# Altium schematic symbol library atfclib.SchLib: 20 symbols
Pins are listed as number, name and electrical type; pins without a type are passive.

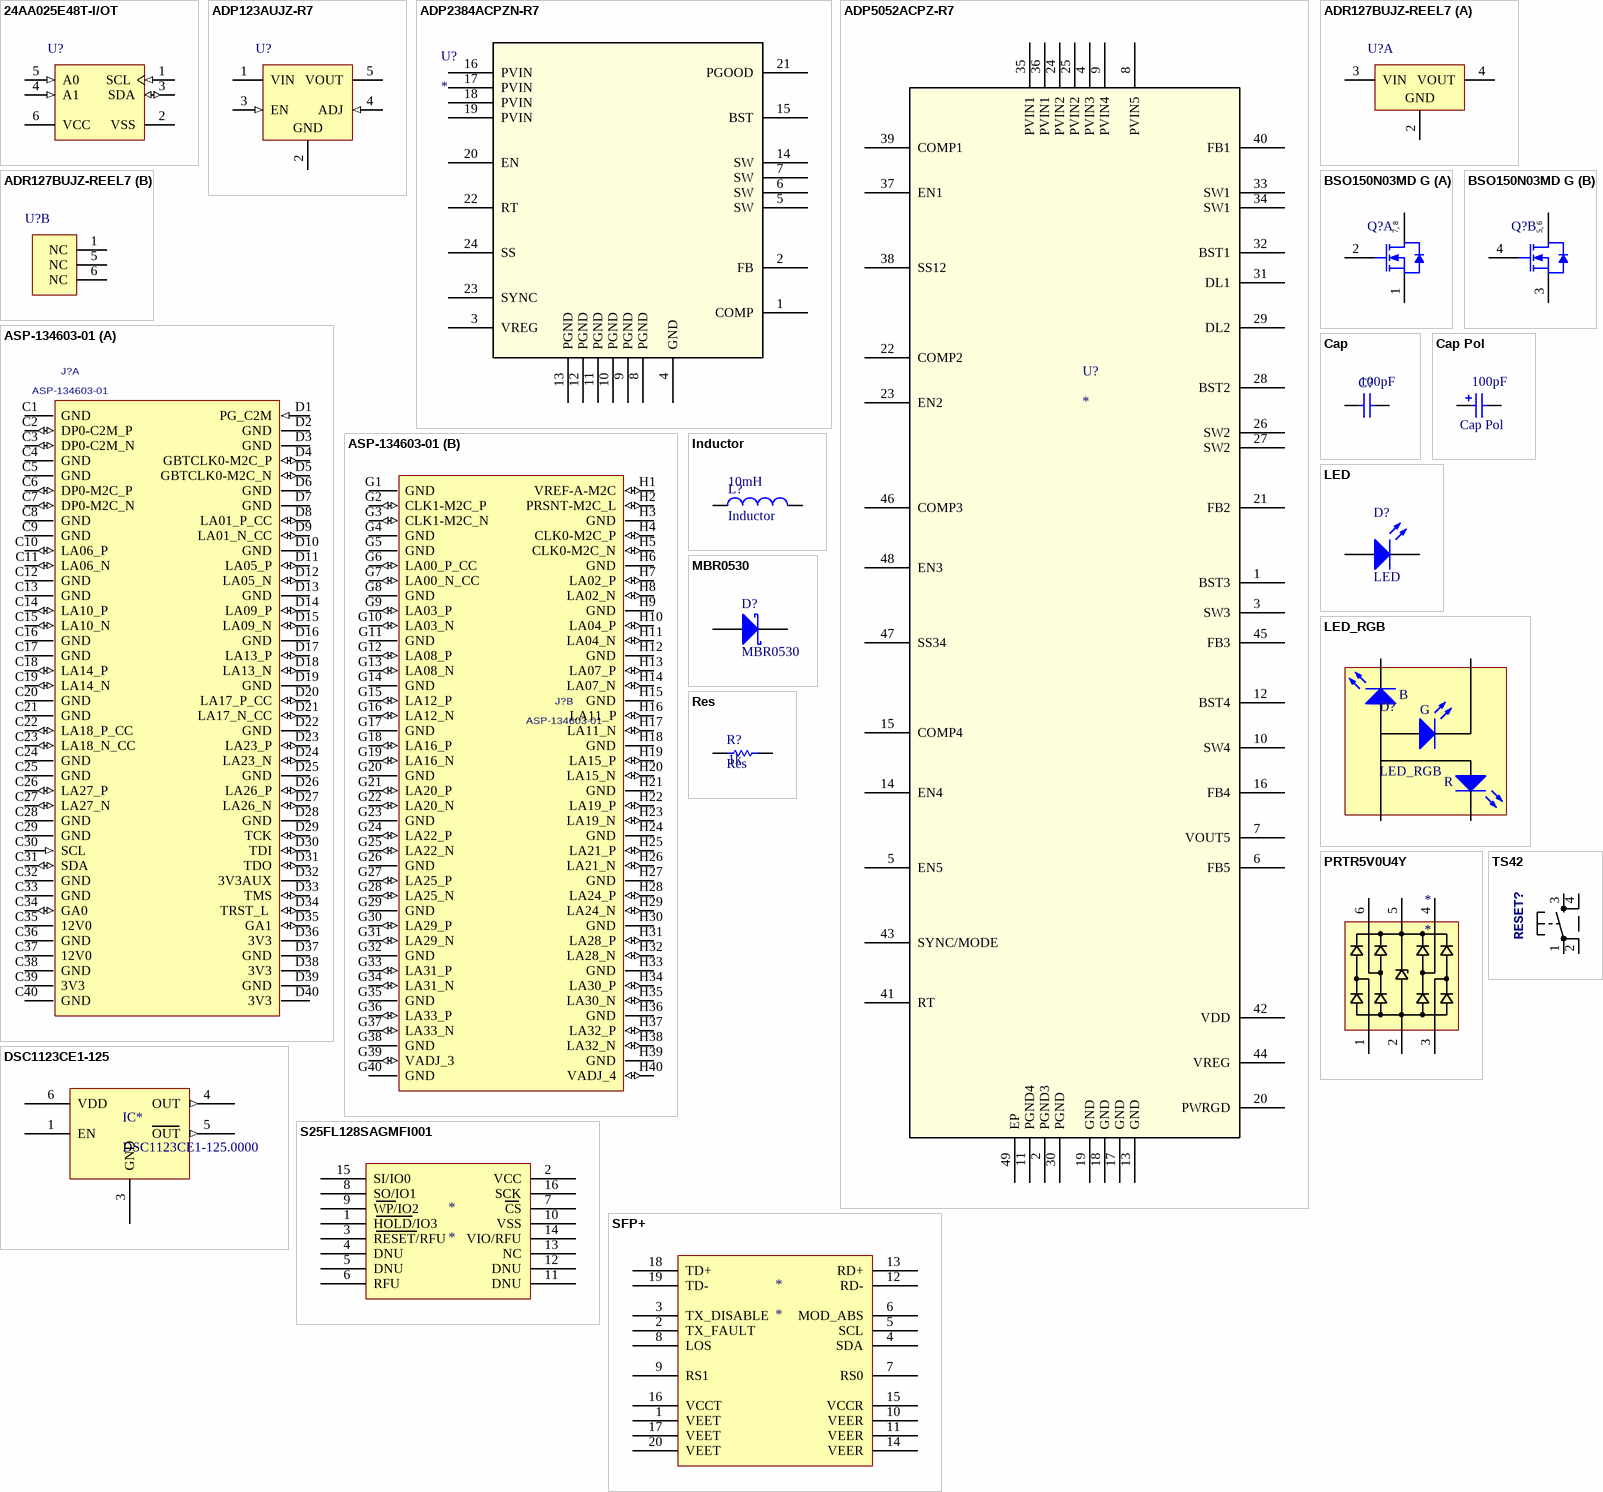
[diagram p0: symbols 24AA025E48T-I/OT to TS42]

## 24AA025E48T-I/OT
designator U?
2K bits I2C™ Serial EEPROM with EUI-48™ Node Identity, 1.7 to 5.5 V, 400 kHz, -40 to 85 degC, 6-pin SOT-23 (OT6), Tape and Reel; Manufacturer: Microchip; PartNumber: 24AA025E48T-I/OT
footprint MCHP-SOT-23-OT6_N (SOT23, 6-Leads, Body 2.9x1.55mm, Pitch 0.95mm, IPC Medium Density)
footprint MCHP-SOT-23-OT6_L (SOT23, 6-Leads, Body 2.9x1.55mm, Pitch 0.95mm, IPC High Density)
footprint MCHP-SOT-23-OT6_M (SOT23, 6-Leads, Body 2.9x1.55mm, Pitch 0.95mm, IPC Low Density)
pins: 1 SCL (in) "Serial Clock", 2 VSS (power) "Ground", 3 SDA (io) "Serial Address/Data I/O", 4 A1 (in) "Chip Address Input", 5 A0 (in) "Chip Address Input", 6 VCC (power) "+1.7V to 5.5V Power Supply"

## ADP123AUJZ-R7
designator U?
300 mA, Low Quiescent Current, CMOS Linear Regulator, 2.3 to 5.5 V Vin, 0.8 to 5 V Vout, Industrial, 5-pin SOT23 (UJ-5), Reel; Manufacturer: Analog Devices; PartNumber: ADP123AUJZ-R7; Iout max: 300mA; Supply Current IGND @ Small Load: 45uA; Vin (max) (V): 5.5; Vin (min) (V): 2.3; Vout Adjustable Range: 0.8V to 5V
footprint ADI-UJ-5_N (SOT23, 5-Leads, Body 2.9x1.6mm, Pitch 0.95mm, IPC Medium Density)
footprint ADI-UJ-5_L (SOT23, 5-Leads, Body 2.9x1.6mm, Pitch 0.95mm, IPC High Density)
footprint ADI-UJ-5_M (SOT23, 5-Leads, Body 2.9x1.6mm, Pitch 0.95mm, IPC Low Density)
pins: 1 VIN (power) "Regulator Input Supply. Bypass VIN to GND with a capacitor of at least 1 uF.", 2 GND (power) "Ground.", 3 EN (in) "Enable Input. Drive EN high to turn on the regulator; drive EN low to turn off the regulator. For automatic startup, connect EN to VIN.", 4 ADJ (in) "Output Voltage Adjust Pin. Connect the midpoint of the voltage divider between VOUT and GND to this pin to set the output voltage.", 5 VOUT (power) "Regulated Output Voltage. Bypass VOUT to GND with a capacitor of at least 1 uF."

## ADP2384ACPZN-R7
designator U?
Imported
footprint CP_24_12
pins: 1 COMP, 2 FB, 3 VREG, 4 GND, 5 SW, 6 SW, 7 SW, 8 PGND, 9 PGND, 10 PGND, 11 PGND, 12 PGND, 13 PGND, 14 SW, 15 BST, 16 PVIN, 17 PVIN, 18 PVIN, 19 PVIN, 20 EN, 21 PGOOD, 22 RT, 23 SYNC, 24 SS

## ADP5052ACPZ-R7
designator U?
Imported
footprint CP_48_13
pins: 1 BST3, 2 PGND3, 3 SW3, 4 PVIN3, 5 EN5, 6 FB5, 7 VOUT5, 8 PVIN5, 9 PVIN4, 10 SW4, 11 PGND4, 12 BST4, 13 GND, 14 EN4, 15 COMP4, 16 FB4, 17 GND, 18 GND, 19 GND, 20 PWRGD, 21 FB2, 22 COMP2, 23 EN2, 24 PVIN2, 25 PVIN2, 26 SW2, 27 SW2, 28 BST2, 29 DL2, 30 PGND, 31 DL1, 32 BST1, 33 SW1, 34 SW1, 35 PVIN1, 36 PVIN1, 37 EN1, 38 SS12, 39 COMP1, 40 FB1, 41 RT, 42 VDD, 43 SYNC/MODE, 44 VREG, 45 FB3, 46 COMP3, 47 SS34, 48 EN3, 49 EP

## ADR127BUJZ-REEL7
designator U?
Precision, Micropower LDO Voltage Reference in TSOT, 1.25 V Output, 2.7 to 18 V Supply, Industrial, 6-pin SOT23 (UJ-6), Reel; Manufacturer: Analog Devices; PartNumber: ADR127BUJZ-REEL7; Max V Supply (V): 18; Min V Supply (V): 2.7; Ref Out TC (ppm/C): 3; Vout: 1.25V
footprint ADI-UJ-6_N (SOT23, 6-Leads, Body 2.9x1.6mm, Pitch 0.95mm, IPC Medium Density)
footprint ADI-UJ-6_L (SOT23, 6-Leads, Body 2.9x1.6mm, Pitch 0.95mm, IPC High Density)
footprint ADI-UJ-6_M (SOT23, 6-Leads, Body 2.9x1.6mm, Pitch 0.95mm, IPC Low Density)
part A pins: 2 GND (power), 3 VIN (power), 4 VOUT (power)
part B pins: 1 NC, 5 NC, 6 NC

## ASP-134603-01
designator J?
0.050" PITCH SOCKET ARRAY ASSEMBLY.; MANUFACTURER: SAMTEC
footprint ASP-134603-01
part A pins: C1 GND, C2 DP0-C2M_P (io), C3 DP0-C2M_N (io), C4 GND, C5 GND, C6 DP0-M2C_P (io), C7 DP0-M2C_N (io), C8 GND, C9 GND, C10 LA06_P (io), C11 LA06_N (io), C12 GND, C13 GND, C14 LA10_P (io), C15 LA10_N (io), C16 GND, C17 GND, C18 LA14_P (io), C19 LA14_N (io), C20 GND, C21 GND, C22 LA18_P_CC (io), C23 LA18_N_CC (io), C24 GND, C25 GND, C26 LA27_P (io), C27 LA27_N (io), C28 GND, C29 GND, C30 SCL (in), C31 SDA (io), C32 GND, C33 GND, C34 GA0 (io), C35 12V0, C36 GND, C37 12V0, C38 GND, C39 3V3, C40 GND, D1 PG_C2M (in), D2 GND, D3 GND, D4 GBTCLK0-M2C_P (io), D5 GBTCLK0-M2C_N (io), D6 GND, D7 GND, D8 LA01_P_CC (io), D9 LA01_N_CC (io), D10 GND, D11 LA05_P (io), D12 LA05_N (io), D13 GND, D14 LA09_P (io), D15 LA09_N (io), D16 GND, D17 LA13_P (io), D18 LA13_N (io), D19 GND, D20 LA17_P_CC (io), D21 LA17_N_CC (io), D22 GND, D23 LA23_P (io), D24 LA23_N (io), D25 GND, D26 LA26_P (io), D27 LA26_N (io), D28 GND, D29 TCK (io), D30 TDI (io), D31 TDO (io), D32 3V3AUX, D33 TMS (io), D34 TRST_L  (io), D35 GA1 (io), D36 3V3, D37 GND, D38 3V3, D39 GND, D40 3V3
part B pins: G1 GND, G2 CLK1-M2C_P (io), G3 CLK1-M2C_N (io), G4 GND, G5 GND, G6 LA00_P_CC (io), G7 LA00_N_CC (io), G8 GND, G9 LA03_P (io), G10 LA03_N (io), G11 GND, G12 LA08_P (io), G13 LA08_N (io), G14 GND, G15 LA12_P (io), G16 LA12_N (io), G17 GND, G18 LA16_P (io), G19 LA16_N (io), G20 GND, G21 LA20_P (io), G22 LA20_N (io), G23 GND, G24 LA22_P (io), G25 LA22_N (io), G26 GND, G27 LA25_P (io), G28 LA25_N (io), G29 GND, G30 LA29_P (io), G31 LA29_N (io), G32 GND, G33 LA31_P (io), G34 LA31_N (io), G35 GND, G36 LA33_P (io), G37 LA33_N (io), G38 GND, G39 VADJ_3 (io), G40 GND, H1 VREF-A-M2C (io), H2 PRSNT-M2C_L (io), H3 GND, H4 CLK0-M2C_P (io), H5 CLK0-M2C_N (io), H6 GND, H7 LA02_P (io), H8 LA02_N (io), H9 GND, H10 LA04_P (io), H11 LA04_N (io), H12 GND, H13 LA07_P (io), H14 LA07_N (io), H15 GND, H16 LA11_P (io), H17 LA11_N (io), H18 GND, H19 LA15_P (io), H20 LA15_N (io), H21 GND, H22 LA19_P (io), H23 LA19_N (io), H24 GND, H25 LA21_P (io), H26 LA21_N (io), H27 GND, H28 LA24_P (io), H29 LA24_N (io), H30 GND, H31 LA28_P (io), H32 LA28_N (io), H33 GND, H34 LA30_P (io), H35 LA30_N (io), H36 GND, H37 LA32_P (io), H38 LA32_N (io), H39 GND, H40 VADJ_4 (io)

## BSO150N03MD G
designator Q?
N-Channel OptiMOS 3 M-Series Power-MOSFET, 30 V VDS, 9.3 A ID, -55 to 150 degC, PG-DSO-8-16, Reel, Green; Manufacturer: Infineon; PartNumber: BSO150N03MD G; Green: TRUE; ID (max): 9.3 A; IDpuls (max): 65 A; Polarity: N; Ptot (max): 2 W; QG: 6.1 nC; RDS (on) (max): 15 mOhm; RDS (on) (max) (@4.5V): 18.2 mOhm; Rth: 50 K/W; RthJA (max): 150 K/W; VDS (max): 30 V; VGS(th) (max): 2 V; VGS(th) (min): 1 V
footprint INF-PG-DSO-8-16_N (SOP, 8-Leads, Body 4.9x3.9mm, Pitch 1.27mm, IPC Medium Density)
footprint INF-PG-DSO-8-16_L (SOP, 8-Leads, Body 4.9x3.9mm, Pitch 1.27mm, IPC High Density)
footprint INF-PG-DSO-8-16_M (SOP, 8-Leads, Body 4.9x3.9mm, Pitch 1.27mm, IPC Low Density)
part A pins: 1 S1, 2 G1, 7 D1, 8 D1
part B pins: 3 S2, 4 G2, 5 D2, 6 D2

## Cap
designator C?  value 100pF
Capacitor
footprint C1210
footprint C1206
footprint C0805
footprint C0603
footprint C0402
pins: 1, 2

## Cap Pol
designator ?  value 100pF
Polarized Capacitor (Surface Mount)
footprint C1206_P
pins: 1, 2
1 alternate drawing of the same symbol

## DSC1123CE1-125
designator IC*, comment DSC1123CE1-125.0000
Standard Clock Oscillators Oscillator Hi Perf -20C-70C 50ppm
footprint DSC1123_32_25
pins: 1 EN, 3 GND, 4 OUT (out), 5 OUT (out), 6 VDD

## Inductor
designator L?  value 10mH
Code_IEC: 1005
footprint MSS1048
footprint SD43
footprint SRP2512
pins: 1, 2

## LED
designator D?
pins: 1 A, 2 K

## LED_RGB
designator D?
Typical INFRARED GaAs LED
footprint ASMB-MTB0-0A3A2
pins: 1 A, 2 B, 3 G, 4 R

## MBR0530
designator D?
footprint SOD-123
pins: 1 K, 2 A

## PRTR5V0U4Y
designator *
footprint SOT363
pins: 1, 2, 3, 4, 5, 6

## Res
designator R?  value 1k
Resistor
footprint R0603
footprint R0402
footprint R0805
pins: 1, 2

## S25FL128SAGMFI001
designator *
footprint SOIC16
pins: 1 HOLD/IO3, 2 VCC, 3 RESET/RFU, 4 DNU, 5 DNU, 6 RFU, 7 CS, 8 SO/IO1, 9 WP/IO2, 10 VSS, 11 DNU, 12 DNU, 13 NC, 14 VIO/RFU, 15 SI/IO0, 16 SCK

## SFP+
designator *
footprint SFP+20
pins: 1 VEET, 2 TX_FAULT, 3 TX_DISABLE, 4 SDA, 5 SCL, 6 MOD_ABS, 7 RS0, 8 LOS, 9 RS1, 10 VEER, 11 VEER, 12 RD-, 13 RD+, 14 VEER, 15 VCCR, 16 VCCT, 17 VEET, 18 TD+, 19 TD-, 20 VEET

## TS42
designator RESET?
PartNo: B3S-1002
footprint B3S-1002
pins: 1, 2, 3, 4

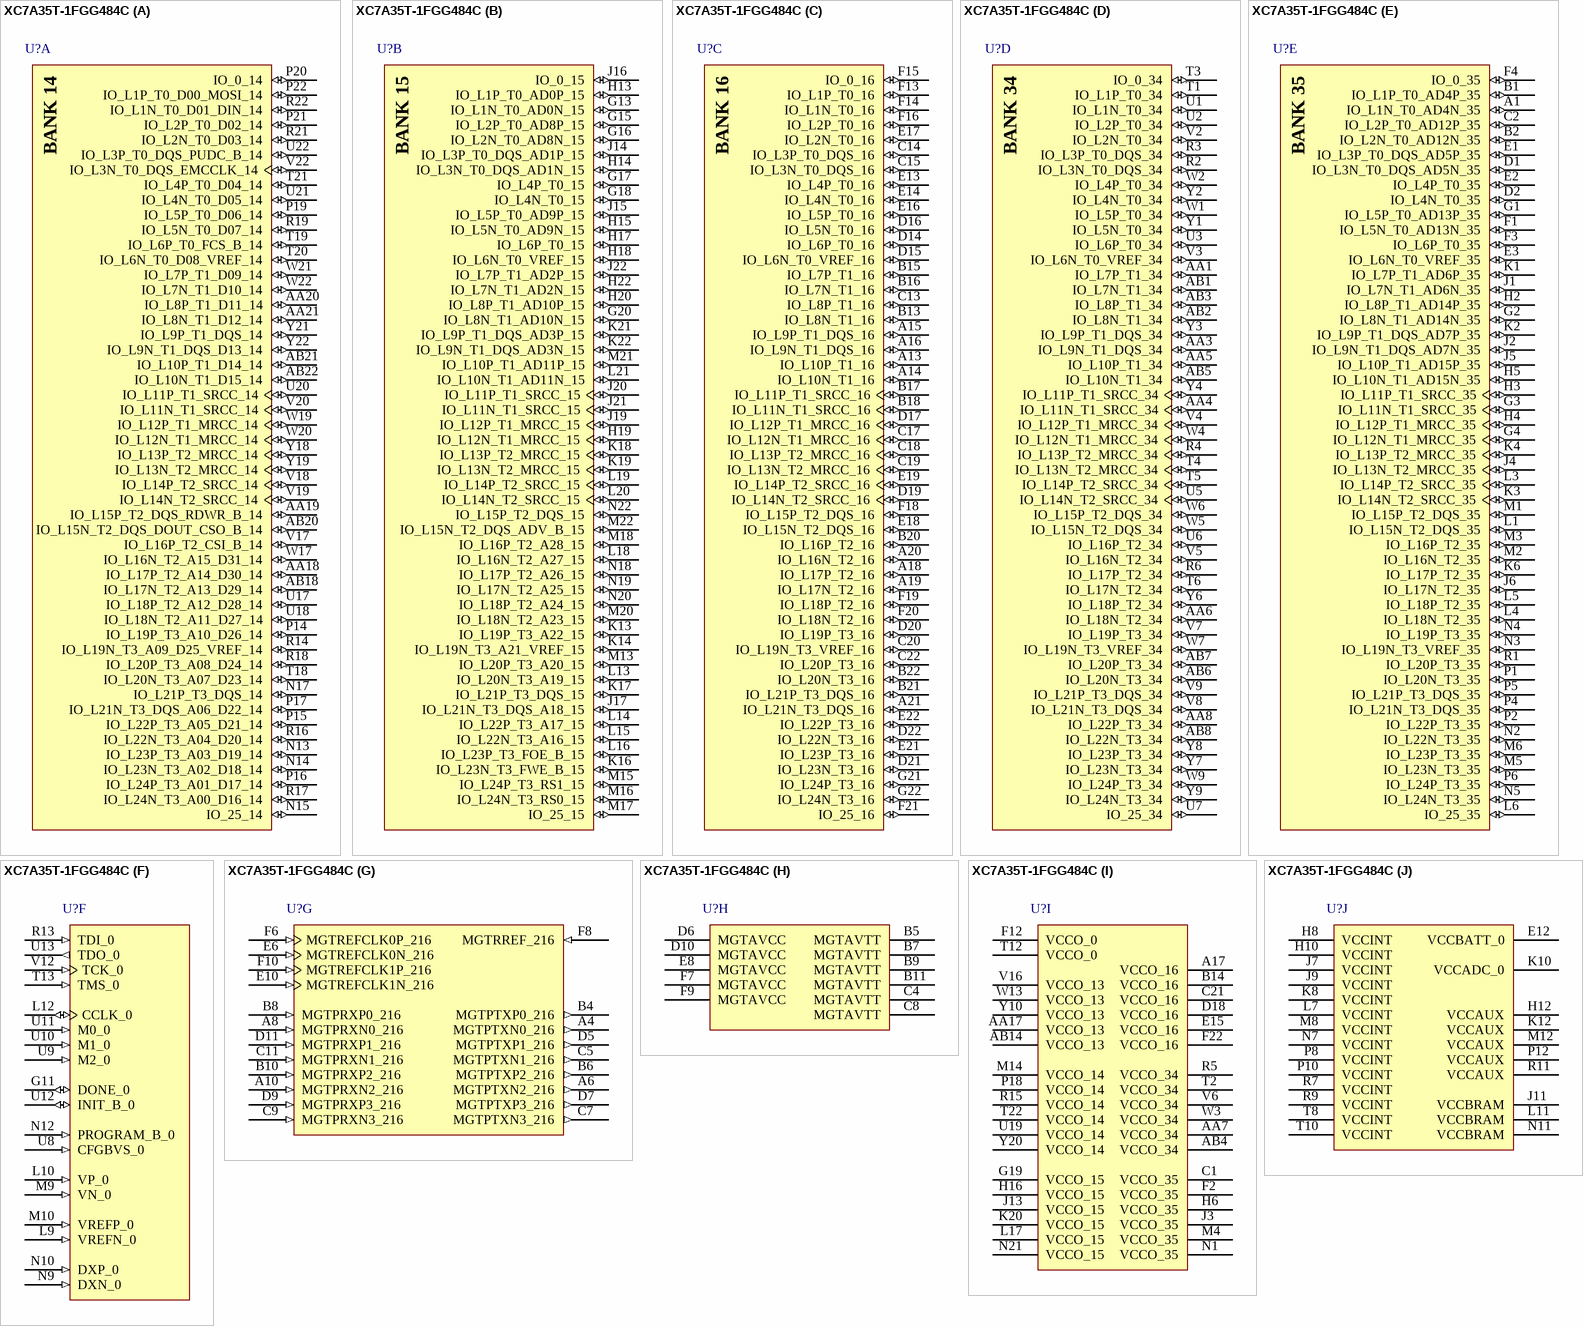
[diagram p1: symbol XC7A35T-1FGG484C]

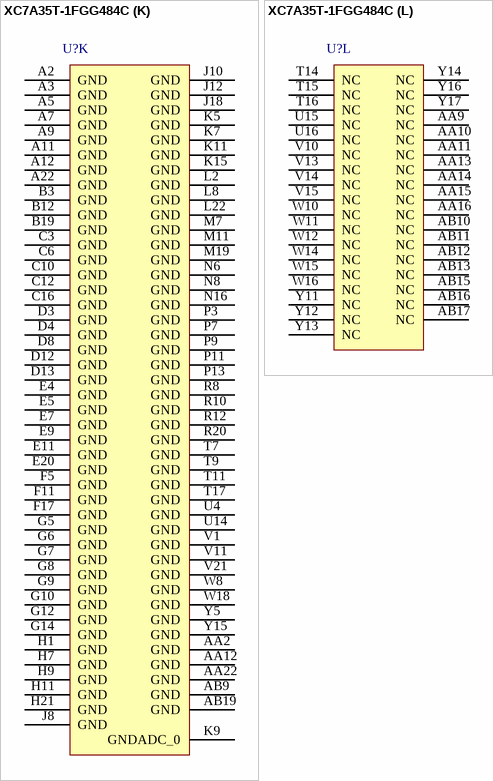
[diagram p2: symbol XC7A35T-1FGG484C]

## XC7A35T-1FGG484C
designator U?
Artix-7 FPGA, 250 User I/Os, 4 GTP, 484-Ball BGA, Speed Grade 1, Commercial Grade, Pb-Free; Manufacturer: Xilinx; Total Block RAM: 1800 Kb; GTP: 4; Clock Mgmt Tiles (CMTs): 5; Logic Cells: 33280; Available User I/O: 250; Speed Grades: 1; NexusDeviceID: XC7A35T-1FGG484C
footprint FGG484 (BGA, 484-Balls, Body 23x23mm, Pitch 1mm)
part A pins: AA18 IO_L17P_T2_A14_D30_14 (io), AA19 IO_L15P_T2_DQS_RDWR_B_14 (io), AA20 IO_L8P_T1_D11_14 (io), AA21 IO_L8N_T1_D12_14 (io), AB18 IO_L17N_T2_A13_D29_14 (io), AB20 IO_L15N_T2_DQS_DOUT_CSO_B_14 (io), AB21 IO_L10P_T1_D14_14 (io), AB22 IO_L10N_T1_D15_14 (io), N13 IO_L23P_T3_A03_D19_14 (io), N14 IO_L23N_T3_A02_D18_14 (io), N15 IO_25_14 (io), N17 IO_L21P_T3_DQS_14 (io), P14 IO_L19P_T3_A10_D26_14 (io), P15 IO_L22P_T3_A05_D21_14 (io), P16 IO_L24P_T3_A01_D17_14 (io), P17 IO_L21N_T3_DQS_A06_D22_14 (io), P19 IO_L5P_T0_D06_14 (io), P20 IO_0_14 (io), P21 IO_L2P_T0_D02_14 (io), P22 IO_L1P_T0_D00_MOSI_14 (io), R14 IO_L19N_T3_A09_D25_VREF_14 (io), R16 IO_L22N_T3_A04_D20_14 (io), R17 IO_L24N_T3_A00_D16_14 (io), R18 IO_L20P_T3_A08_D24_14 (io), R19 IO_L5N_T0_D07_14 (io), R21 IO_L2N_T0_D03_14 (io), R22 IO_L1N_T0_D01_DIN_14 (io), T18 IO_L20N_T3_A07_D23_14 (io), T19 IO_L6P_T0_FCS_B_14 (io), T20 IO_L6N_T0_D08_VREF_14 (io), T21 IO_L4P_T0_D04_14 (io), U17 IO_L18P_T2_A12_D28_14 (io), U18 IO_L18N_T2_A11_D27_14 (io), U20 IO_L11P_T1_SRCC_14 (io), U21 IO_L4N_T0_D05_14 (io), U22 IO_L3P_T0_DQS_PUDC_B_14 (io), V17 IO_L16P_T2_CSI_B_14 (io), V18 IO_L14P_T2_SRCC_14 (io), V19 IO_L14N_T2_SRCC_14 (io), V20 IO_L11N_T1_SRCC_14 (io), V22 IO_L3N_T0_DQS_EMCCLK_14 (io), W17 IO_L16N_T2_A15_D31_14 (io), W19 IO_L12P_T1_MRCC_14 (io), W20 IO_L12N_T1_MRCC_14 (io), W21 IO_L7P_T1_D09_14 (io), W22 IO_L7N_T1_D10_14 (io), Y18 IO_L13P_T2_MRCC_14 (io), Y19 IO_L13N_T2_MRCC_14 (io), Y21 IO_L9P_T1_DQS_14 (io), Y22 IO_L9N_T1_DQS_D13_14 (io)
part B pins: G13 IO_L1N_T0_AD0N_15 (io), G15 IO_L2P_T0_AD8P_15 (io), G16 IO_L2N_T0_AD8N_15 (io), G17 IO_L4P_T0_15 (io), G18 IO_L4N_T0_15 (io), G20 IO_L8N_T1_AD10N_15 (io), H13 IO_L1P_T0_AD0P_15 (io), H14 IO_L3N_T0_DQS_AD1N_15 (io), H15 IO_L5N_T0_AD9N_15 (io), H17 IO_L6P_T0_15 (io), H18 IO_L6N_T0_VREF_15 (io), H19 IO_L12N_T1_MRCC_15 (io), H20 IO_L8P_T1_AD10P_15 (io), H22 IO_L7N_T1_AD2N_15 (io), J14 IO_L3P_T0_DQS_AD1P_15 (io), J15 IO_L5P_T0_AD9P_15 (io), J16 IO_0_15 (io), J17 IO_L21N_T3_DQS_A18_15 (io), J19 IO_L12P_T1_MRCC_15 (io), J20 IO_L11P_T1_SRCC_15 (io), J21 IO_L11N_T1_SRCC_15 (io), J22 IO_L7P_T1_AD2P_15 (io), K13 IO_L19P_T3_A22_15 (io), K14 IO_L19N_T3_A21_VREF_15 (io), K16 IO_L23N_T3_FWE_B_15 (io), K17 IO_L21P_T3_DQS_15 (io), K18 IO_L13P_T2_MRCC_15 (io), K19 IO_L13N_T2_MRCC_15 (io), K21 IO_L9P_T1_DQS_AD3P_15 (io), K22 IO_L9N_T1_DQS_AD3N_15 (io), L13 IO_L20N_T3_A19_15 (io), L14 IO_L22P_T3_A17_15 (io), L15 IO_L22N_T3_A16_15 (io), L16 IO_L23P_T3_FOE_B_15 (io), L18 IO_L16N_T2_A27_15 (io), L19 IO_L14P_T2_SRCC_15 (io), L20 IO_L14N_T2_SRCC_15 (io), L21 IO_L10N_T1_AD11N_15 (io), M13 IO_L20P_T3_A20_15 (io), M15 IO_L24P_T3_RS1_15 (io), M16 IO_L24N_T3_RS0_15 (io), M17 IO_25_15 (io), M18 IO_L16P_T2_A28_15 (io), M20 IO_L18N_T2_A23_15 (io), M21 IO_L10P_T1_AD11P_15 (io), M22 IO_L15N_T2_DQS_ADV_B_15 (io), N18 IO_L17P_T2_A26_15 (io), N19 IO_L17N_T2_A25_15 (io), N20 IO_L18P_T2_A24_15 (io), N22 IO_L15P_T2_DQS_15 (io)
part C pins: A13 IO_L10P_T1_16 (io), A14 IO_L10N_T1_16 (io), A15 IO_L9P_T1_DQS_16 (io), A16 IO_L9N_T1_DQS_16 (io), A18 IO_L17P_T2_16 (io), A19 IO_L17N_T2_16 (io), A20 IO_L16N_T2_16 (io), A21 IO_L21N_T3_DQS_16 (io), B13 IO_L8N_T1_16 (io), B15 IO_L7P_T1_16 (io), B16 IO_L7N_T1_16 (io), B17 IO_L11P_T1_SRCC_16 (io), B18 IO_L11N_T1_SRCC_16 (io), B20 IO_L16P_T2_16 (io), B21 IO_L21P_T3_DQS_16 (io), B22 IO_L20N_T3_16 (io), C13 IO_L8P_T1_16 (io), C14 IO_L3P_T0_DQS_16 (io), C15 IO_L3N_T0_DQS_16 (io), C17 IO_L12N_T1_MRCC_16 (io), C18 IO_L13P_T2_MRCC_16 (io), C19 IO_L13N_T2_MRCC_16 (io), C20 IO_L19N_T3_VREF_16 (io), C22 IO_L20P_T3_16 (io), D14 IO_L6P_T0_16 (io), D15 IO_L6N_T0_VREF_16 (io), D16 IO_L5N_T0_16 (io), D17 IO_L12P_T1_MRCC_16 (io), D19 IO_L14N_T2_SRCC_16 (io), D20 IO_L19P_T3_16 (io), D21 IO_L23N_T3_16 (io), D22 IO_L22N_T3_16 (io), E13 IO_L4P_T0_16 (io), E14 IO_L4N_T0_16 (io), E16 IO_L5P_T0_16 (io), E17 IO_L2N_T0_16 (io), E18 IO_L15N_T2_DQS_16 (io), E19 IO_L14P_T2_SRCC_16 (io), E21 IO_L23P_T3_16 (io), E22 IO_L22P_T3_16 (io), F13 IO_L1P_T0_16 (io), F14 IO_L1N_T0_16 (io), F15 IO_0_16 (io), F16 IO_L2P_T0_16 (io), F18 IO_L15P_T2_DQS_16 (io), F19 IO_L18P_T2_16 (io), F20 IO_L18N_T2_16 (io), F21 IO_25_16 (io), G21 IO_L24P_T3_16 (io), G22 IO_L24N_T3_16 (io)
part D pins: AA1 IO_L7P_T1_34 (io), AA3 IO_L9N_T1_DQS_34 (io), AA4 IO_L11N_T1_SRCC_34 (io), AA5 IO_L10P_T1_34 (io), AA6 IO_L18N_T2_34 (io), AA8 IO_L22P_T3_34 (io), AB1 IO_L7N_T1_34 (io), AB2 IO_L8N_T1_34 (io), AB3 IO_L8P_T1_34 (io), AB5 IO_L10N_T1_34 (io), AB6 IO_L20N_T3_34 (io), AB7 IO_L20P_T3_34 (io), AB8 IO_L22N_T3_34 (io), R2 IO_L3N_T0_DQS_34 (io), R3 IO_L3P_T0_DQS_34 (io), R4 IO_L13P_T2_MRCC_34 (io), R6 IO_L17P_T2_34 (io), T1 IO_L1P_T0_34 (io), T3 IO_0_34 (io), T4 IO_L13N_T2_MRCC_34 (io), T5 IO_L14P_T2_SRCC_34 (io), T6 IO_L17N_T2_34 (io), U1 IO_L1N_T0_34 (io), U2 IO_L2P_T0_34 (io), U3 IO_L6P_T0_34 (io), U5 IO_L14N_T2_SRCC_34 (io), U6 IO_L16P_T2_34 (io), U7 IO_25_34 (io), V2 IO_L2N_T0_34 (io), V3 IO_L6N_T0_VREF_34 (io), V4 IO_L12P_T1_MRCC_34 (io), V5 IO_L16N_T2_34 (io), V7 IO_L19P_T3_34 (io), V8 IO_L21N_T3_DQS_34 (io), V9 IO_L21P_T3_DQS_34 (io), W1 IO_L5P_T0_34 (io), W2 IO_L4P_T0_34 (io), W4 IO_L12N_T1_MRCC_34 (io), W5 IO_L15N_T2_DQS_34 (io), W6 IO_L15P_T2_DQS_34 (io), W7 IO_L19N_T3_VREF_34 (io), W9 IO_L24P_T3_34 (io), Y1 IO_L5N_T0_34 (io), Y2 IO_L4N_T0_34 (io), Y3 IO_L9P_T1_DQS_34 (io), Y4 IO_L11P_T1_SRCC_34 (io), Y6 IO_L18P_T2_34 (io), Y7 IO_L23N_T3_34 (io), Y8 IO_L23P_T3_34 (io), Y9 IO_L24N_T3_34 (io)
part E pins: A1 IO_L1N_T0_AD4N_35 (io), B1 IO_L1P_T0_AD4P_35 (io), B2 IO_L2N_T0_AD12N_35 (io), C2 IO_L2P_T0_AD12P_35 (io), D1 IO_L3N_T0_DQS_AD5N_35 (io), D2 IO_L4N_T0_35 (io), E1 IO_L3P_T0_DQS_AD5P_35 (io), E2 IO_L4P_T0_35 (io), E3 IO_L6N_T0_VREF_35 (io), F1 IO_L5N_T0_AD13N_35 (io), F3 IO_L6P_T0_35 (io), F4 IO_0_35 (io), G1 IO_L5P_T0_AD13P_35 (io), G2 IO_L8N_T1_AD14N_35 (io), G3 IO_L11N_T1_SRCC_35 (io), G4 IO_L12N_T1_MRCC_35 (io), H2 IO_L8P_T1_AD14P_35 (io), H3 IO_L11P_T1_SRCC_35 (io), H4 IO_L12P_T1_MRCC_35 (io), H5 IO_L10N_T1_AD15N_35 (io), J1 IO_L7N_T1_AD6N_35 (io), J2 IO_L9N_T1_DQS_AD7N_35 (io), J4 IO_L13N_T2_MRCC_35 (io), J5 IO_L10P_T1_AD15P_35 (io), J6 IO_L17N_T2_35 (io), K1 IO_L7P_T1_AD6P_35 (io), K2 IO_L9P_T1_DQS_AD7P_35 (io), K3 IO_L14N_T2_SRCC_35 (io), K4 IO_L13P_T2_MRCC_35 (io), K6 IO_L17P_T2_35 (io), L1 IO_L15N_T2_DQS_35 (io), L3 IO_L14P_T2_SRCC_35 (io), L4 IO_L18N_T2_35 (io), L5 IO_L18P_T2_35 (io), L6 IO_25_35 (io), M1 IO_L15P_T2_DQS_35 (io), M2 IO_L16N_T2_35 (io), M3 IO_L16P_T2_35 (io), M5 IO_L23N_T3_35 (io), M6 IO_L23P_T3_35 (io), N2 IO_L22N_T3_35 (io), N3 IO_L19N_T3_VREF_35 (io), N4 IO_L19P_T3_35 (io), N5 IO_L24N_T3_35 (io), P1 IO_L20N_T3_35 (io), P2 IO_L22P_T3_35 (io), P4 IO_L21N_T3_DQS_35 (io), P5 IO_L21P_T3_DQS_35 (io), P6 IO_L24P_T3_35 (io), R1 IO_L20P_T3_35 (io)
part F pins: G11 DONE_0 (io), L9 VREFN_0 (in), L10 VP_0 (in), L12 CCLK_0 (io), M9 VN_0 (in), M10 VREFP_0 (in), N9 DXN_0 (in), N10 DXP_0 (in), N12 PROGRAM_B_0 (in), R13 TDI_0 (in), T13 TMS_0 (in), U8 CFGBVS_0 (in), U9 M2_0 (in), U10 M1_0 (in), U11 M0_0 (in), U12 INIT_B_0 (io), U13 TDO_0 (out), V12 TCK_0 (in)
part G pins: A4 MGTPTXN0_216 (out), A6 MGTPTXN2_216 (out), A8 MGTPRXN0_216 (in), A10 MGTPRXN2_216 (in), B4 MGTPTXP0_216 (out), B6 MGTPTXP2_216 (out), B8 MGTPRXP0_216 (in), B10 MGTPRXP2_216 (in), C5 MGTPTXN1_216 (out), C7 MGTPTXN3_216 (out), C9 MGTPRXN3_216 (in), C11 MGTPRXN1_216 (in), D5 MGTPTXP1_216 (out), D7 MGTPTXP3_216 (out), D9 MGTPRXP3_216 (in), D11 MGTPRXP1_216 (in), E6 MGTREFCLK0N_216 (in), E10 MGTREFCLK1N_216 (in), F6 MGTREFCLK0P_216 (in), F8 MGTRREF_216 (in), F10 MGTREFCLK1P_216 (in)
part H pins: B5 MGTAVTT (power), B7 MGTAVTT (power), B9 MGTAVTT (power), B11 MGTAVTT (power), C4 MGTAVTT (power), C8 MGTAVTT (power), D6 MGTAVCC (power), D10 MGTAVCC (power), E8 MGTAVCC (power), F7 MGTAVCC (power), F9 MGTAVCC (power)
part I pins: A17 VCCO_16 (power), AA7 VCCO_34 (power), AA17 VCCO_13 (power), AB4 VCCO_34 (power), AB14 VCCO_13 (power), B14 VCCO_16 (power), C1 VCCO_35 (power), C21 VCCO_16 (power), D18 VCCO_16 (power), E15 VCCO_16 (power), F2 VCCO_35 (power), F12 VCCO_0 (power), F22 VCCO_16 (power), G19 VCCO_15 (power), H6 VCCO_35 (power), H16 VCCO_15 (power), J3 VCCO_35 (power), J13 VCCO_15 (power), K20 VCCO_15 (power), L17 VCCO_15 (power), M4 VCCO_35 (power), M14 VCCO_14 (power), N1 VCCO_35 (power), N21 VCCO_15 (power), P18 VCCO_14 (power), R5 VCCO_34 (power), R15 VCCO_14 (power), T2 VCCO_34 (power), T12 VCCO_0 (power), T22 VCCO_14 (power), U19 VCCO_14 (power), V6 VCCO_34 (power), V16 VCCO_13 (power), W3 VCCO_34 (power), W13 VCCO_13 (power), Y10 VCCO_13 (power), Y20 VCCO_14 (power)
part J pins: E12 VCCBATT_0 (power), H8 VCCINT (power), H10 VCCINT (power), H12 VCCAUX (power), J7 VCCINT (power), J9 VCCINT (power), J11 VCCBRAM (power), K8 VCCINT (power), K10 VCCADC_0 (power), K12 VCCAUX (power), L7 VCCINT (power), L11 VCCBRAM (power), M8 VCCINT (power), M12 VCCAUX (power), N7 VCCINT (power), N11 VCCBRAM (power), P8 VCCINT (power), P10 VCCINT (power), P12 VCCAUX (power), R7 VCCINT (power), R9 VCCINT (power), R11 VCCAUX (power), T8 VCCINT (power), T10 VCCINT (power)
part K pins: A2 GND (power), A3 GND (power), A5 GND (power), A7 GND (power), A9 GND (power), A11 GND (power), A12 GND (power), A22 GND (power), AA2 GND (power), AA12 GND (power), AA22 GND (power), AB9 GND (power), AB19 GND (power), B3 GND (power), B12 GND (power), B19 GND (power), C3 GND (power), C6 GND (power), C10 GND (power), C12 GND (power), C16 GND (power), D3 GND (power), D4 GND (power), D8 GND (power), D12 GND (power), D13 GND (power), E4 GND (power), E5 GND (power), E7 GND (power), E9 GND (power), E11 GND (power), E20 GND (power), F5 GND (power), F11 GND (power), F17 GND (power), G5 GND (power), G6 GND (power), G7 GND (power), G8 GND (power), G9 GND (power), G10 GND (power), G12 GND (power), G14 GND (power), H1 GND (power), H7 GND (power), H9 GND (power), H11 GND (power), H21 GND (power), J8 GND (power), J10 GND (power), J12 GND (power), J18 GND (power), K5 GND (power), K7 GND (power), K9 GNDADC_0 (power), K11 GND (power), K15 GND (power), L2 GND (power), L8 GND (power), L22 GND (power), M7 GND (power), M11 GND (power), M19 GND (power), N6 GND (power), N8 GND (power), N16 GND (power), P3 GND (power), P7 GND (power), P9 GND (power), P11 GND (power), P13 GND (power), R8 GND (power), R10 GND (power), R12 GND (power), R20 GND (power), T7 GND (power), T9 GND (power), T11 GND (power), T17 GND (power), U4 GND (power), U14 GND (power), V1 GND (power), V11 GND (power), V21 GND (power), W8 GND (power), W18 GND (power), Y5 GND (power), Y15 GND (power)
part L pins: AA9 NC, AA10 NC, AA11 NC, AA13 NC, AA14 NC, AA15 NC, AA16 NC, AB10 NC, AB11 NC, AB12 NC, AB13 NC, AB15 NC, AB16 NC, AB17 NC, T14 NC, T15 NC, T16 NC, U15 NC, U16 NC, V10 NC, V13 NC, V14 NC, V15 NC, W10 NC, W11 NC, W12 NC, W14 NC, W15 NC, W16 NC, Y11 NC, Y12 NC, Y13 NC, Y14 NC, Y16 NC, Y17 NC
